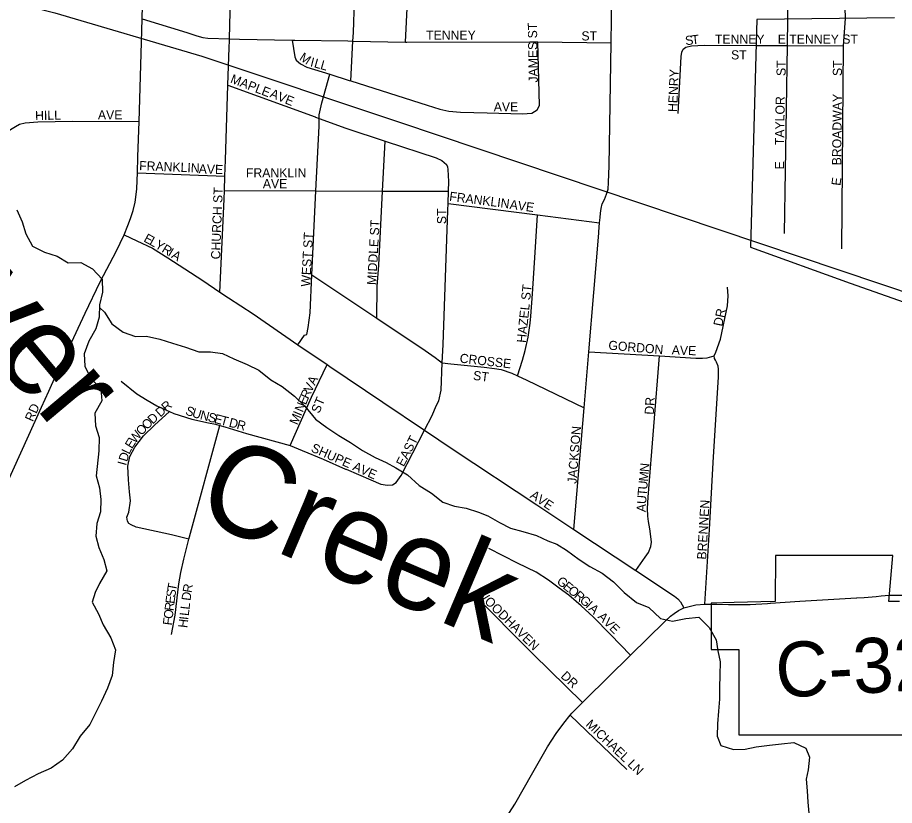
# Model space of a CAD drawing. Extents: x 1857828 to 2277390, y 930619 to 1324581.
# Drawn here: x 2042796 to 2047591, y 1233563 to 1237869 of the extents above; entities that cross this region are included whole.
import ezdxf

# ---------------------------------------------------------------- set-up
doc = ezdxf.new("R2010")
doc.units = 0
for name, color, linetype in [('GM_X_City_Street', 7, 'Continuous'), ('GM_X_City_Street_Text', 7, 'Continuous'), ('GM_X_Corporation', 7, 'Continuous'), ('GM_X_County_Road', 7, 'Continuous'), ('GM_X_County_Road_Text', 7, 'Continuous'), ('GM_X_Minor_River', 7, 'Continuous'), ('GM_X_Minor_River_Text', 7, 'Continuous'), ('GM_X_Rail_Line', 7, 'Continuous'), ('GM_X_Township_Road', 7, 'Continuous'), ('GM_X_Township_Subdivision', 7, 'Continuous'), ('GM_X_Township_Subdivision_Text', 7, 'Continuous')]:
    doc.layers.add(name, color=color, linetype=linetype)

msp = doc.modelspace()

# ---------------------------------------------------------------- linework, layer by layer
at = {"layer": 'GM_X_City_Street'}
for points in [[(2044618.9, 1237522.3), (2044630.2, 1237740.4), (2044632.6, 1237787.3), (2044643.1, 1238131.7), (2044645.1, 1238197), (2044658.7, 1238486.3), (2044663.5, 1238626.9), (2044670.5, 1238920)], [(2043954.4, 1237741.8), (2043954.5, 1237743.1), (2043954.7, 1237752.2), (2043961.1, 1237975.3), (2043960.7, 1238139.9), (2043959.8, 1238481.7)], [(2043471.2, 1237671.4), (2043476.9, 1237861.4), (2043481.2, 1238005.8), (2043485.3, 1238145.6)], [(2044917.6, 1237735.3), (2044936.5, 1238105.4), (2044936.5, 1238106.5)], [(2045974, 1236690.8), (2045974.5, 1236697.7), (2045978.7, 1236747.9), (2045981.1, 1236776.4), (2045983.1, 1236800.5), (2045987.1, 1236824.7), (2045993.1, 1236850.7), (2046005.1, 1236874.9), (2046017.1, 1236903), (2046025.1, 1236931.1), (2046027.1, 1236967.3), (2046031, 1237057.7), (2046041.9, 1237731.1), (2046048.1, 1238114.9)], [(2047008.5, 1237859.7), (2047004.4, 1238103.5)], [(2047323.3, 1237863.8), (2047317.3, 1238099.8)], [(2043476.9, 1237861.4), (2043722.1, 1237786.8), (2043776.4, 1237769.1), (2043808.6, 1237759.3), (2043836.7, 1237755.5), (2043954.7, 1237752.2), (2044009.2, 1237750.7), (2044298.2, 1237745.9), (2044303.4, 1237745.9), (2044312.2, 1237745.7)], [(2043902.8, 1236368.5), (2043926.5, 1236876.6), (2043927.8, 1236923), (2043930.1, 1237001.3), (2043932.7, 1237089.5), (2043946.5, 1237499.6), (2043953.4, 1237706.1), (2043954.4, 1237741.8)], [(2044298.2, 1237745.9), (2044312.9, 1237654.5), (2044319, 1237636.5), (2044343.3, 1237616.6), (2044377.5, 1237598.7), (2044503.9, 1237558.7), (2044608.6, 1237525.6)], [(2044312.2, 1237745.7), (2044602.9, 1237740.9), (2044630.2, 1237740.4), (2044917.6, 1237735.3), (2044923.9, 1237735.2), (2045597.7, 1237736), (2045641.9, 1237735.5), (2046041.9, 1237731.1)], [(2045637.1, 1237364.8), (2045650.9, 1237389), (2045641.9, 1237735.5)], [(2043448.7, 1236933.7), (2043448.8, 1236935.4), (2043451.6, 1237020.4), (2043454.4, 1237106.9), (2043460.2, 1237300.6), (2043471.2, 1237671), (2043471.2, 1237671.4)], [(2046409.4, 1237344.2), (2046423, 1237621.4), (2046424.7, 1237655.6), (2046428.6, 1237679.7), (2046436.4, 1237695.8), (2046450.4, 1237708), (2046482.4, 1237714.2), (2046550.5, 1237718.7)], [(2046550.5, 1237718.7), (2046835.6, 1237717.1)], [(2044445.2, 1237306.2), (2044445.2, 1237307), (2044445.5, 1237317.9), (2044445.9, 1237338.2), (2044459.4, 1237402.5), (2044503.9, 1237558.7)], [(2043946.5, 1237499.6), (2044423.9, 1237325.7), (2044425.4, 1237325.2)], [(2044608.6, 1237525.6), (2044610.2, 1237525.1), (2044618.9, 1237522.3), (2045035.1, 1237390.6), (2045105.5, 1237369), (2045153.8, 1237357.3), (2045218, 1237351.7), (2045364.4, 1237348.8), (2045557, 1237342.1), (2045609.1, 1237346.5), (2045637.1, 1237364.8)], [(2042556.9, 1237077.6), (2042680.3, 1237197), (2042722.1, 1237231.4), (2042758, 1237257.8), (2042783.9, 1237274), (2042805.8, 1237286.2), (2042837.8, 1237294.5), (2042906, 1237299), (2043096.5, 1237302.4), (2043460.2, 1237300.6)], [(2044328.9, 1236081.2), (2044364.1, 1236132.8), (2044378.1, 1236136.9), (2044385.8, 1236175.1), (2044395.1, 1236255.5), (2044405.1, 1236462.5), (2044427.3, 1236921.5), (2044444.5, 1237275.9), (2044445.2, 1237306.2)], [(2044425.4, 1237325.2), (2044445.5, 1237317.9), (2044591, 1237264.9), (2044806.2, 1237193.9), (2045085.8, 1237101.8), (2045116, 1237087.9), (2045142.2, 1237066)], [(2044760.6, 1236225.3), (2044762.9, 1236398.7), (2044771.9, 1236515.2), (2044792.4, 1236920.4), (2044806.2, 1237193.9)], [(2045149.3, 1236814.4), (2045149.4, 1236816.7), (2045150.7, 1236853.4), (2045153.1, 1236919.3), (2045155.1, 1236973.8), (2045150.1, 1237037.8), (2045148, 1237053.1), (2045142.2, 1237066)], [(2043451.6, 1237020.4), (2043930.1, 1237001.3)], [(2043284.4, 1236493.7), (2043334.5, 1236590.7), (2043378.6, 1236681.1), (2043398.6, 1236733.3), (2043412.6, 1236771.5), (2043428.7, 1236813.6), (2043438.6, 1236859.9), (2043448.6, 1236930.2), (2043448.7, 1236933.7)], [(2043927.8, 1236923), (2044427.3, 1236921.5), (2044792.4, 1236920.4), (2045153.1, 1236919.3)], [(2044846.5, 1235314.9), (2044866.4, 1235327.1), (2044894.2, 1235365.5), (2045022.1, 1235613.2), (2045063.8, 1235694), (2045085.4, 1235746.3), (2045099.2, 1235774.6), (2045112.7, 1235832.9), (2045118.7, 1235982.1), (2045122.6, 1236082), (2045149.3, 1236814.4)], [(2045150.7, 1236853.4), (2045638.9, 1236791.2), (2045978.7, 1236747.9)], [(2045602, 1236236.2), (2045602, 1236236.6), (2045611.6, 1236358.6), (2045625.7, 1236585.6), (2045638.9, 1236791.2)], [(2043378.6, 1236681.1), (2043448.9, 1236648.9), (2043533.3, 1236608.7), (2043617.7, 1236556.5), (2043710.2, 1236496.1), (2043808.6, 1236431.8), (2043902.8, 1236368.5), (2043949.3, 1236337.3), (2044084, 1236248.9), (2044328.9, 1236081.2), (2044488.3, 1235972.2), (2044504, 1235961.4), (2044793.4, 1235766.4), (2045022.1, 1235613.2), (2045177.3, 1235509.1), (2045635.5, 1235205.6), (2045838.2, 1235071.5), (2046176.8, 1234847.6), (2046389.1, 1234707.1), (2046407.3, 1234693), (2046421.3, 1234674.9), (2046439.4, 1234642.8)], [(2045838.2, 1235071.5), (2045894, 1235736.8), (2045919.6, 1236042.5), (2045974, 1236690.8)], [(2042620.7, 1235068), (2042925.8, 1235739.1), (2042965.9, 1235827.4), (2043005.9, 1235911.8), (2043078.1, 1236066.5), (2043166.2, 1236253.3), (2043248.3, 1236424), (2043284.2, 1236493.5), (2043284.4, 1236493.7)], [(2044405.1, 1236462.5), (2044760.6, 1236225.3), (2045024.7, 1236049.1), (2045079.1, 1236011.4), (2045103.1, 1235993.7), (2045104, 1235993)], [(2046612.3, 1235996.6), (2046607.4, 1236006.3), (2046605.3, 1236020.3), (2046615.1, 1236040.5), (2046640.6, 1236110.9), (2046679.1, 1236293.9), (2046682.7, 1236348.2), (2046678.3, 1236396.3)], [(2045529, 1235911.7), (2045556.6, 1235996.7), (2045572.2, 1236049), (2045587.6, 1236121.4), (2045599, 1236197.8), (2045602, 1236236.2)], [(2045919.6, 1236042.5), (2046307, 1236019.4), (2046505.1, 1236007.5), (2046541.2, 1236007.8), (2046567.3, 1236010), (2046605.3, 1236020.3)], [(2045104, 1235993), (2045118.7, 1235982.1), (2045165.7, 1235975.8), (2045348.3, 1235959.1), (2045404.5, 1235951.5), (2045440.7, 1235945.7), (2045499, 1235926), (2045529, 1235911.7), (2045581.6, 1235886.5), (2045894, 1235736.8)], [(2046176.8, 1234847.6), (2046227.7, 1234919.2), (2046245.5, 1234945.4), (2046259.3, 1234977.6), (2046263.1, 1235001.8), (2046258.8, 1235031.9), (2046254.5, 1235074), (2046246.1, 1235114.1), (2046241.8, 1235144.2), (2046241.4, 1235186.4), (2046244.9, 1235248.6), (2046307, 1236019.4)], [(2046554.7, 1234663.2), (2046579.4, 1235070.3), (2046600.3, 1235437.9), (2046628.3, 1235906), (2046630, 1235948.2), (2046627.8, 1235964.3), (2046617.6, 1235986.2), (2046612.5, 1235996.3), (2046612.3, 1235996.6)], [(2044287.1, 1235529.8), (2044403.1, 1235793.7), (2044488.3, 1235972.2)], [(2043361.5, 1235882.6), (2043448.3, 1235812.9), (2043504.7, 1235777.2), (2043557.2, 1235747.4), (2043593.2, 1235731.3), (2043593.5, 1235731.2)], [(2043732.3, 1235018.1), (2043637.4, 1235041.2), (2043444.6, 1235084), (2043416.4, 1235095.8), (2043404.3, 1235103.8), (2043396.1, 1235115.8), (2043393.9, 1235137.9), (2043403.7, 1235166), (2043413.2, 1235228.3), (2043408.8, 1235276.5), (2043402.2, 1235342.7), (2043399.6, 1235417), (2043409.1, 1235469.3), (2043436.8, 1235521.7), (2043484.4, 1235582.3), (2043544, 1235640.9), (2043626, 1235716.6)], [(2043593.5, 1235731.2), (2043626, 1235716.6), (2043649.8, 1235705.9), (2043748.3, 1235674.5), (2043840.8, 1235653.1), (2043878.9, 1235647.4), (2043902.5, 1235640), (2043929.2, 1235631.6), (2044047.8, 1235596.3), (2044287.1, 1235529.8)], [(2043638.1, 1234497), (2043657.3, 1234603.6), (2043672.3, 1234728.2), (2043677.9, 1234774.4), (2043689.4, 1234836.7), (2043704.8, 1234909.1), (2043732.3, 1235018.1), (2043735.8, 1235031.8), (2043902.5, 1235640)], [(2044287.1, 1235529.8), (2044351.5, 1235502.2), (2044466.2, 1235454.8), (2044590, 1235401.5)], [(2044590, 1235401.5), (2044592, 1235400.6), (2044727.9, 1235342.2), (2044782.3, 1235318.5), (2044818.4, 1235312.7), (2044846.5, 1235314.9)], [(2046147.6, 1234384.2), (2046038.2, 1234496.7), (2045943.4, 1234594.6), (2045878.9, 1234654.6), (2045810.4, 1234712.5), (2045758, 1234750.4), (2045699.6, 1234794.3), (2045631.2, 1234838.2), (2045530.7, 1234887.9), (2045373.8, 1234967.5)], [(2045885, 1234125.6), (2045615.8, 1234390.4), (2045283, 1234722.2)], [(2045414.6, 1233413.7), (2045514.9, 1233570.4), (2045613.1, 1233743.1), (2045693.2, 1233883.7), (2045741.3, 1233956), (2045783.5, 1234012.2), (2045818.7, 1234055.6), (2045827.6, 1234066.5), (2045885, 1234125.6), (2045901.8, 1234142.8), (2046147.6, 1234384.2), (2046335.1, 1234568.5), (2046351.1, 1234582.5), (2046351.7, 1234583.1)], [(2045818.7, 1234055.6), (2046128.7, 1233760.2)]]:
    msp.add_lwpolyline(points, dxfattribs=at)
at = {"layer": 'GM_X_Corporation'}
for points in [[(2047591.8, 1237867.4), (2046839.7, 1237857.5), (2046803.9, 1236614.5), (2047348.6, 1236416.5), (2048167.1, 1236128.9)], [(2047619.9, 1234677.2), (2047559.8, 1234677.2), (2047581.9, 1234928.9), (2046941.4, 1234929), (2046938.4, 1234677.4), (2046861, 1234675.8), (2046715.6, 1234672.6), (2046589.8, 1234668.1), (2046589.8, 1234414.9), (2046739.9, 1234414.9), (2046739.8, 1233949.5), (2048106.6, 1233949.4)]]:
    msp.add_lwpolyline(points, dxfattribs=at)
at = {"layer": 'GM_X_County_Road'}
for points in [[(2046911.7, 1234667.8), (2046913.5, 1234667.9), (2047074.6, 1234678.6), (2047384.1, 1234697.5), (2047385.6, 1234697.6)], [(2047385.6, 1234697.6), (2047426.1, 1234700.1), (2047490.8, 1234705.6)], [(2047490.8, 1234705.6), (2047491.3, 1234705.6), (2047518.4, 1234708), (2047562.6, 1234711.9), (2047602.8, 1234711.8), (2047649, 1234711.7), (2047707.2, 1234711.6), (2047777.5, 1234701.5), (2048122.1, 1234676.9)], [(2046439.4, 1234642.8), (2046504.3, 1234659.5), (2046554.7, 1234663.2), (2046558.5, 1234663.5), (2046620.8, 1234663.3), (2046683, 1234661.2), (2046753.3, 1234661.1), (2046801.5, 1234661), (2046897.9, 1234666.9), (2046911.7, 1234667.8)]]:
    msp.add_lwpolyline(points, dxfattribs=at)
at = {"layer": 'GM_X_Minor_River'}
for points in [[(2042791.1, 1236818.5), (2042821.8, 1236752.4), (2042840.4, 1236686.2), (2042877.1, 1236620.2), (2042943.7, 1236586.5), (2043012.1, 1236564.9), (2043072.7, 1236529.1), (2043140.9, 1236529.6), (2043205.4, 1236495.9), (2043258.1, 1236440), (2043260.7, 1236367.7), (2043243.3, 1236299.2), (2043241.8, 1236230.9), (2043224.3, 1236168.5), (2043184.7, 1236099.9), (2043159.2, 1236031.4), (2043163.8, 1235963.2), (2043196.5, 1235897.1), (2043251.2, 1235839.2), (2043255.8, 1235774.9), (2043218.2, 1235706.4), (2043222.8, 1235638.1), (2043241.4, 1235573.9), (2043240, 1235501.6), (2043225.1, 1235364.9), (2043243.8, 1235298.7), (2043250.3, 1235234.4), (2043248.9, 1235168.1), (2043229.4, 1235103.7), (2043223.9, 1235035.4), (2043240.5, 1234973.2), (2043267.2, 1234907.1), (2043283.8, 1234844.9), (2043244.2, 1234776.3), (2043220.6, 1234725.9), (2043202.9, 1234673.6), (2043237.6, 1234609.5), (2043264.2, 1234549.4), (2043305, 1234479.4), (2043331.6, 1234413.3), (2043320.2, 1234344.9), (2043312.8, 1234272.5), (2043287.3, 1234204), (2043255.7, 1234133.5), (2043222.2, 1234067), (2043190.6, 1234004.5), (2043138.9, 1233941.8), (2043095.3, 1233873.2), (2043041.7, 1233810.6), (2042979.8, 1233765.9), (2042907.8, 1233735.3), (2042839.9, 1233698.7), (2042779.9, 1233664.1)], [(2043243, 1236284.9), (2043271.7, 1236259.2), (2043310.4, 1236195.2), (2043373, 1236149.4), (2043441.5, 1236125.8), (2043501.7, 1236128.2), (2043574.1, 1236110.6), (2043642.6, 1236089), (2043715, 1236067.4), (2043787.5, 1236041.8), (2043851.7, 1236042.2), (2043916.1, 1236032.6), (2043978.6, 1236002.9), (2044051.1, 1235973.2), (2044115.6, 1235941.5), (2044180.3, 1235889.7), (2044242.8, 1235852), (2044309.5, 1235800.2), (2044366.2, 1235744.3), (2044425, 1235674.4), (2044487.7, 1235628.6), (2044552.3, 1235584.9), (2044616.8, 1235547.1), (2044681.5, 1235503.4), (2044752.1, 1235463.7), (2044812.5, 1235438), (2044865, 1235408.2), (2044927.5, 1235370.4), (2044992.3, 1235310.6), (2045058.9, 1235268.9), (2045121.5, 1235221.1), (2045186, 1235199.4), (2045248.3, 1235187.8), (2045316.7, 1235166.2), (2045367.1, 1235146.4), (2045431.6, 1235108.7), (2045492.1, 1235079), (2045558.5, 1235059.3), (2045633, 1235037.7), (2045695.5, 1235010), (2045745.8, 1234990.3), (2045798.3, 1234958.5), (2045867, 1234906.7), (2045925.6, 1234868.9), (2045992.1, 1234833.2), (2046054.7, 1234785.4), (2046113.5, 1234727.6), (2046180.2, 1234671.8), (2046248.7, 1234644.1), (2046311.4, 1234584.3), (2046377.8, 1234570.7), (2046449.9, 1234585.2), (2046522.2, 1234591.8), (2046578.9, 1234535.9), (2046615.6, 1234467.8), (2046626.1, 1234407.6), (2046638.7, 1234347.4), (2046637.3, 1234275.1), (2046633.9, 1234206.8), (2046634.4, 1234144.5), (2046628.9, 1234078.1), (2046623.5, 1234009.8), (2046622.1, 1233941.5), (2046642.6, 1233891.4), (2046711, 1233867.8), (2046775.3, 1233870.2), (2046835.4, 1233882.6), (2046907.6, 1233893.2), (2046973.8, 1233899.7), (2047042, 1233906.2), (2047106.4, 1233876.5), (2047127, 1233826.4), (2047119.5, 1233758), (2047107.9, 1233705.7), (2047114.5, 1233643.5), (2047117, 1233581.2), (2047123.5, 1233521)]]:
    msp.add_lwpolyline(points, dxfattribs=at)
at = {"layer": 'GM_X_Rail_Line'}
msp.add_lwpolyline([(2010250.7, 1246105.6), (2015802.6, 1244725.6), (2020567.6, 1243531.6), (2023679.8, 1242724.2), (2028101.7, 1241626.9), (2032683.1, 1240476.3), (2034089.4, 1240128.3), (2037647.8, 1239223.2), (2041004.2, 1238402), (2042999.3, 1237895.6), (2043803.3, 1237657.3), (2044879.5, 1237299.8), (2048172.1, 1236193.5), (2051939.6, 1234938.6)], dxfattribs=at)
at = {"layer": 'GM_X_Township_Road'}
msp.add_lwpolyline([(2046351.7, 1234583.1), (2046367.2, 1234596.6), (2046387.2, 1234612.7), (2046411.3, 1234628.7), (2046439.4, 1234642.8)], dxfattribs=at)
at = {"layer": 'GM_X_Township_Subdivision'}
for points in [[(2047302.9, 1236604.4), (2047312.9, 1237714.6), (2047323.3, 1237863.8)], [(2046990.4, 1236688.2), (2047006.3, 1237716.2), (2047008.5, 1237859.7)], [(2046835.6, 1237717.1), (2047006.3, 1237716.2), (2047312.9, 1237714.6)]]:
    msp.add_lwpolyline(points, dxfattribs=at)

# ---------------------------------------------------------------- texts
at = {"layer": 'GM_X_City_Street_Text'}
for s, rotation, p in [('JAMES ST', 90.909, (2045641.3, 1237514.1)), ('TENNEY', 0, (2045030.4, 1237748.1)), ('ST', 0, (2045879.5, 1237743.7)), ('S', 7.5621, (2046450.1, 1237717.2)), ('T', 6.0204, (2046484.6, 1237721.8)), ('TENNEY', 0, (2046609.9, 1237726.1)), ('M', 326.5424, (2044332.9, 1237639.7)), ('ST', 0, (2046697.9, 1237640.1)), ('I', 345.7053, (2044393.3, 1237603.3)), ('L', 344.1147, (2044414.2, 1237598)), ('L', 344.3888, (2044448.3, 1237588.3)), ('HENRY', 87.6156, (2046402.6, 1237351.9)), ('MAPLE', 338.8783, (2043955.7, 1237514.3)), ('AVE', 337.845, (2044171.5, 1237435)), ('AVE', 0, (2045400, 1237356.5)), ('HILL', 1.3571, (2042892.3, 1237308.1)), ('AVE', 0, (2043235.2, 1237312.5)), ('FRANKLIN', 357.5473, (2043460, 1237035.3)), ('AVE', 358.0261, (2043785.5, 1237017.7)), ('FRANKLIN', 0, (2044044.7, 1236995.7)), ('AVE', 0, (2044137.1, 1236936.1)), ('CHURCH ST', 87.7987, (2043903.3, 1236546.7)), ('FRANKLIN', 352.6775, (2045154.8, 1236868)), ('AVE', 352.1518, (2045484.8, 1236824)), ('ST', 90, (2045139.8, 1236739.9)), ('MIDDLE ST', 86.9046, (2044757, 1236406)), ('E', 331.5901, (2043481.6, 1236647)), ('L', 330.8313, (2043512.4, 1236630.3)), ('WEST ST', 86.985, (2044396.2, 1236397.2)), ('Y', 328.9538, (2043542.8, 1236613.4)), ('R', 328.5071, (2043580.4, 1236590.8)), ('I', 328.444, (2043614.1, 1236570.1)), ('A', 328.4888, (2043632.9, 1236558.6)), ('HAZEL ST', 84.2062, (2045575.4, 1236089.6)), ('DR', 78.116, (2046649.3, 1236178.6)), ('GORDON', 355.1588, (2046025.5, 1236054.1)), ('AVE', 358.0261, (2046372.7, 1236027.7)), ('CROSSE', 353.412, (2045211.8, 1235983.7)), ('A', 63.4349, (2044421.6, 1235855.8)), ('ST', 352.8531, (2045284.8, 1235889.5)), ('V', 63.5327, (2044402, 1235816.5)), ('E', 67.3465, (2044372.2, 1235748.8)), ('R', 65.3029, (2044385.6, 1235780.8)), ('RD', 66.0353, (2042879, 1235656.9)), ('R', 41.8554, (2043609.4, 1235712)), ('N', 67.3465, (2044355.3, 1235708.2)), ('ST', 66.7995, (2044445.2, 1235702.1)), ('DR', 86.9896, (2046274.9, 1235697.6)), ('D', 41.8767, (2043576.7, 1235682.6)), ('S', 338.9899, (2043709.6, 1235701.4)), ('U', 343.5453, (2043746.6, 1235687.4)), ('N', 345.5601, (2043790.6, 1235674.4)), ('S', 345.586, (2043833.3, 1235663.4)), ('M', 67.3465, (2044326.5, 1235639.1)), ('I', 67.3465, (2044346.8, 1235687.8)), ('O', 44.6445, (2043503.6, 1235613.5)), ('D', 42.5883, (2043534.6, 1235644.1)), ('E', 345.5331, (2043867.3, 1235654.6)), ('T', 345.5664, (2043901.5, 1235645.8)), ('D', 345.5466, (2043948.3, 1235633.8)), ('R', 345.549, (2043990.9, 1235622.8)), ('W', 51.8522, (2043439.4, 1235537.6)), ('O', 47.025, (2043474, 1235581.7)), ('JACKSON', 85.4615, (2045852.6, 1235319.4)), ('E', 57.8788, (2043421.5, 1235508.9)), ('EAST', 62.7065, (2044907.6, 1235411)), ('SHUPE AVE', 336.1177, (2044396.7, 1235498.7)), ('D', 72.4843, (2043394.4, 1235438.3)), ('L', 64.3393, (2043406.9, 1235478.5)), ('I', 74.7334, (2043388.8, 1235417.5)), ('N', 84.6881, (2046247.9, 1235384)), ('M', 84.6918, (2046243, 1235331.4)), ('U', 84.7027, (2046239, 1235287.6)), ('AVE', 326.3099, (2045594.4, 1235247.4)), ('T', 85.0776, (2046235.9, 1235252.6)), ('U', 86.5, (2046233.3, 1235209)), ('BRENNEN', 86.5305, (2046561.2, 1234905.6)), ('A', 86.939, (2046230.9, 1235165.2)), ('G', 320.6983, (2045740.3, 1234780.4)), ('T', 79.5045, (2043662.4, 1234732.4)), ('R', 80.5856, (2043747.2, 1234722.7)), ('WOODHAVEN', 315.4439, (2045301, 1234718.2)), ('E', 320.6491, (2045774.3, 1234752.5)), ('O', 320.7202, (2045801.6, 1234730.2)), ('E', 83.1814, (2043653.5, 1234663.4)), ('S', 82.2176, (2043657.7, 1234698.1)), ('D', 82.3923, (2043741.4, 1234679.5)), ('R', 320.6576, (2045835.7, 1234702.3)), ('G', 319.1142, (2045866, 1234677.4)), ('R', 83.1881, (2043648.8, 1234624.1)), ('L', 83.2343, (2043735.6, 1234631.7)), ('I', 317.1325, (2045899, 1234648.9)), ('A', 317.009, (2045915.1, 1234634)), ('O', 83.1624, (2043643.6, 1234580.4)), ('L', 83.3949, (2043731.6, 1234596.8)), ('AVE', 314.9948, (2045965.4, 1234590.6)), ('F', 83.18, (2043639.4, 1234545.4)), ('H', 83.3629, (2043723.9, 1234531.2)), ('I', 83.3412, (2043729, 1234574.9)), ('DR', 317.1199, (2045762.7, 1234265.2)), ('MICHAEL LN', 316.4213, (2045899.2, 1234001.1))]:
    msp.add_text(s, height=50, rotation=rotation, dxfattribs=at).set_placement(p)
at = {"layer": 'GM_X_County_Road_Text'}
msp.add_text('C-32', height=300, rotation=2.9387, dxfattribs=at).set_placement((2046948, 1234151.5))
at = {"layer": 'GM_X_Minor_River_Text'}
for s, height, rotation, p in [('Beaver', 500.3, 309.9928, (2041669.4, 1237191.8)), ('Creek', 500.29, 336.993, (2043751.7, 1235143.5))]:
    msp.add_text(s, height=height, rotation=rotation, dxfattribs=at).set_placement(p)
at = {"layer": 'GM_X_Township_Subdivision_Text'}
for s, rotation, p in [('E TENNEY ST', 0, (2046953.2, 1237726.1)), ('ST', 90, (2046996.5, 1237549.5)), ('ST', 90, (2047304.5, 1237549.5)), ('TAYLOR', 89.1324, (2046987.7, 1237171.2)), ('BROADWAY', 89.3775, (2047300.1, 1237061.2)), ('E', 90, (2046987.8, 1237039.1)), ('E', 82.875, (2047295.8, 1236947.9))]:
    msp.add_text(s, height=50, rotation=rotation, dxfattribs=at).set_placement(p)

doc.saveas('drawing.dxf')
